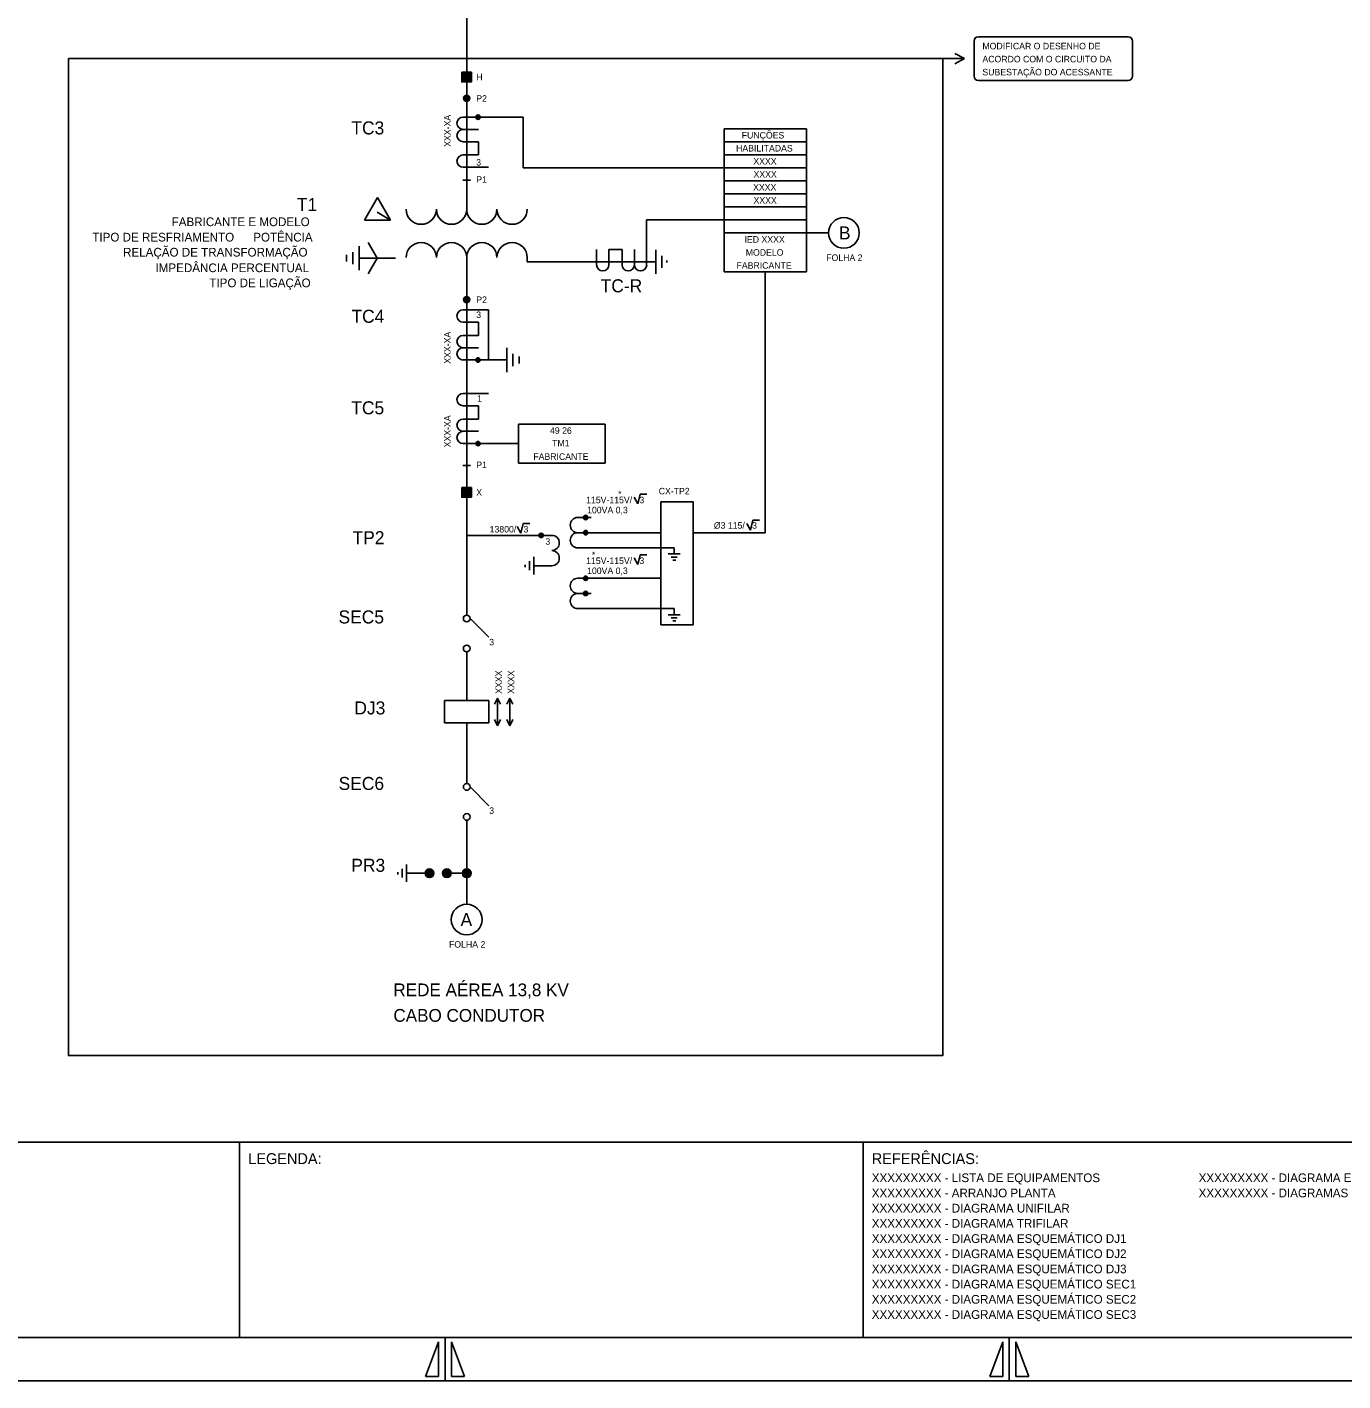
# Model space of a CAD drawing. Extents: x 400 to 1404, y 358 to 952.
# Drawn here: x 807.3 to 1110.5, y 358 to 669.8 of the extents above; entities that cross this region are included whole.
import ezdxf

# ---------------------------------------------------------------- set-up
doc = ezdxf.new("R2010")
doc.units = 0
doc.layers.add('New Level (0)', color=7, linetype='Continuous')

# ---------------------------------------------------------------- blocks, each defined once
blk = doc.blocks.new('_U3')
for p, q in [((-1.47, 0.42), (-0.62, -1.12)), ((-0.62, -1.12), (-0.07, 1.12)), ((-0.07, 1.12), (1.47, 1.12))]:
    blk.add_line(p, q)

msp = doc.modelspace()

# ---------------------------------------------------------------- linework, layer by layer
for p, q in [((908.57, 627.47), (908.57, 672.04)), ((907.45, 657.26), (909.61, 659.41)), ((907.45, 657.44), (909.43, 659.41)), ((907.45, 657.61), (909.25, 659.41)), ((907.45, 657.79), (909.08, 659.41)), ((907.45, 657.97), (908.9, 659.41)), ((907.45, 658.14), (908.72, 659.41)), ((907.45, 658.32), (908.54, 659.41)), ((907.45, 658.5), (908.37, 659.41)), ((907.45, 658.67), (908.19, 659.41)), ((907.45, 658.85), (908.01, 659.41)), ((907.45, 659.03), (907.84, 659.41)), ((907.45, 659.2), (907.66, 659.41)), ((907.45, 659.38), (907.48, 659.41)), ((907.57, 657.2), (909.66, 659.29)), ((907.75, 657.2), (909.66, 659.12)), ((907.92, 657.2), (909.66, 658.94)), ((908.1, 657.2), (909.66, 658.76)), ((908.28, 657.2), (909.66, 658.59)), ((908.46, 657.2), (909.66, 658.41)), ((908.63, 657.2), (909.66, 658.23)), ((908.81, 657.2), (909.66, 658.06)), ((908.99, 657.2), (909.66, 657.88)), ((909.16, 657.2), (909.66, 657.7)), ((909.34, 657.2), (909.66, 657.53)), ((909.52, 657.2), (909.66, 657.35)), ((907.75, 649.07), (921.57, 649.07)), ((921.57, 637.41), (921.57, 649.07)), ((907.75, 646.24), (911.29, 646.24)), ((967.89, 646.41), (967.89, 613.41)), ((986.87, 646.41), (967.89, 646.41)), ((986.87, 646.41), (986.87, 613.41)), ((907.75, 643.41), (911.29, 643.41)), ((911.29, 640.36), (911.29, 643.41)), ((986.87, 643.41), (967.89, 643.41)), ((907.75, 640.36), (911.29, 640.36)), ((986.87, 640.41), (967.89, 640.41)), ((907.75, 637.53), (913.62, 637.53)), ((921.57, 637.41), (968.49, 637.41)), ((986.87, 637.41), (967.89, 637.41)), ((986.87, 634.41), (967.89, 634.41)), ((884.99, 625.33), (888.02, 630.57)), ((888.02, 630.57), (891.04, 625.33)), ((986.87, 631.41), (967.89, 631.41)), ((891.04, 625.33), (887.95, 627.21)), ((986.87, 628.41), (967.89, 628.41)), ((986.87, 628.41), (967.89, 628.41)), ((891.04, 625.33), (884.99, 625.33)), ((950.04, 615.06), (950.04, 625.41)), ((950.04, 625.41), (967.89, 625.41)), ((986.87, 625.41), (967.89, 625.41)), ((991.94, 622.41), (967.89, 622.41)), ((882.37, 617.99), (882.37, 615.2)), ((883.76, 613.8), (883.76, 619.39)), ((887.95, 616.6), (885.86, 620.22)), ((938.5, 615.06), (938.5, 618.59)), ((941.33, 618.59), (944.38, 618.59)), ((941.33, 615.06), (941.33, 618.59)), ((944.38, 615.06), (944.38, 618.59)), ((947.21, 615.06), (947.21, 618.59)), ((952.16, 618.54), (952.16, 612.96)), ((880.89, 615.82), (880.89, 617.38)), ((892.14, 616.6), (883.76, 616.6)), ((887.95, 616.6), (885.86, 612.97)), ((922.53, 616.71), (922.53, 615.75)), ((922.53, 615.75), (952.16, 615.75)), ((953.55, 614.35), (953.55, 617.15)), ((954.72, 616.09), (954.72, 615.56)), ((986.87, 613.41), (967.89, 613.41)), ((977.38, 553.35), (977.38, 613.41)), ((907.75, 604.68), (913.62, 604.68)), ((907.75, 601.85), (911.29, 601.85)), ((907.75, 598.8), (911.29, 598.8)), ((911.29, 601.85), (911.29, 598.8)), ((907.75, 595.97), (911.29, 595.97)), ((917.81, 590.35), (917.81, 595.93)), ((907.75, 593.14), (911.29, 593.14)), ((911.29, 593.14), (917.81, 593.14)), ((919.2, 594.54), (919.2, 591.74)), ((920.68, 592.36), (920.68, 593.92)), ((907.75, 585.42), (913.62, 585.42)), ((907.75, 582.59), (911.29, 582.59)), ((911.29, 582.59), (911.29, 579.54)), ((907.75, 579.54), (911.29, 579.54)), ((920.5, 578.38), (920.5, 569.38)), ((920.5, 578.38), (940.48, 578.38)), ((940.48, 578.38), (940.48, 569.38)), ((907.75, 576.71), (911.29, 576.71)), ((907.75, 573.88), (920.5, 573.88)), ((907.75, 573.88), (911.29, 573.88)), ((920.5, 569.38), (940.48, 569.38)), ((907.45, 561.58), (909.61, 563.73)), ((907.45, 561.75), (909.43, 563.73)), ((907.45, 561.93), (909.25, 563.73)), ((907.45, 562.11), (909.08, 563.73)), ((907.45, 562.28), (908.9, 563.73)), ((907.45, 562.46), (908.72, 563.73)), ((907.45, 562.64), (908.54, 563.73)), ((907.45, 562.81), (908.37, 563.73)), ((907.45, 562.99), (908.19, 563.73)), ((907.45, 563.17), (908.01, 563.73)), ((907.45, 563.35), (907.84, 563.73)), ((907.45, 563.52), (907.66, 563.73)), ((907.45, 563.7), (907.48, 563.73)), ((907.57, 561.52), (909.66, 563.61)), ((907.75, 561.52), (909.66, 563.44)), ((907.92, 561.52), (909.66, 563.26)), ((908.1, 561.52), (909.66, 563.08)), ((908.28, 561.52), (909.66, 562.9)), ((908.46, 561.52), (909.66, 562.73)), ((908.63, 561.52), (909.66, 562.55)), ((908.81, 561.52), (909.66, 562.37)), ((908.99, 561.52), (909.66, 562.2)), ((909.16, 561.52), (909.66, 562.02)), ((909.34, 561.52), (909.66, 561.84)), ((909.52, 561.52), (909.66, 561.67)), ((934.17, 556.85), (937.28, 556.85)), ((908.58, 552.74), (928.17, 552.74)), ((934.17, 553.35), (953.31, 553.35)), ((960.79, 553.35), (977.38, 553.35)), ((934.17, 549.85), (956.4, 549.85)), ((956.4, 549.85), (956.4, 548.45)), ((922.04, 545.98), (922.04, 545.44)), ((923.05, 544.71), (923.05, 546.76)), ((924.08, 547.78), (924.08, 543.69)), ((957.8, 548.45), (955, 548.45)), ((955.7, 547.75), (957.1, 547.75)), ((956.06, 547.05), (956.74, 547.05)), ((928.17, 545.74), (924.08, 545.74)), ((953.31, 542.86), (934.17, 542.86)), ((934.17, 539.36), (937.28, 539.36)), ((913.67, 529.25), (909.34, 533.59)), ((934.17, 535.86), (956.4, 535.86)), ((957.8, 534.46), (955, 534.46)), ((955.7, 533.76), (957.1, 533.76)), ((956.4, 535.86), (956.4, 534.46)), ((956.06, 533.06), (956.74, 533.06)), ((903.45, 509.59), (903.45, 514.71)), ((903.45, 514.71), (913.69, 514.71)), ((913.69, 514.71), (913.69, 509.59)), ((915.69, 515.25), (914.98, 513.84)), ((915.69, 508.88), (915.69, 515.25)), ((915.69, 515.25), (916.39, 513.84)), ((918.54, 515.25), (917.83, 513.84)), ((918.54, 508.88), (918.54, 515.25)), ((918.54, 515.25), (919.24, 513.84)), ((913.69, 509.59), (903.45, 509.59)), ((915.69, 508.88), (914.98, 510.3)), ((915.69, 508.88), (916.39, 510.3)), ((918.54, 508.88), (917.83, 510.3)), ((918.54, 508.88), (919.24, 510.3)), ((913.68, 490.44), (909.34, 494.78)), ((892.68, 475.19), (892.68, 474.59)), ((892.68, 474.89), (892.68, 474.89)), ((893.68, 475.89), (893.68, 473.89)), ((894.68, 472.89), (894.68, 476.89)), ((896, 474.89), (894.68, 474.89)), ((900, 474.89), (896, 474.89)), ((908.58, 474.89), (904, 474.89))]:
    msp.add_line(p, q)
for points in [[(907.45, 659.41), (909.66, 659.41), (909.66, 657.2), (907.45, 657.2)], [(907.45, 563.73), (909.66, 563.73), (909.66, 561.52), (907.45, 561.52)]]:
    msp.add_lwpolyline(points, close=True)
for centre, radius in [((908.56, 653.41), 0.729), ((908.57, 653.4), 0.511), ((908.57, 653.4), 0.288), ((911.2, 649.07), 0.511), ((911.2, 649.07), 0.288), ((908.56, 607.04), 0.729), ((908.57, 607.04), 0.511), ((908.57, 607.04), 0.288), ((911.2, 593.14), 0.511), ((911.2, 593.14), 0.288), ((911.2, 573.88), 0.511), ((911.2, 573.88), 0.288), ((935.97, 556.85), 0.511), ((935.97, 556.85), 0.288), ((925.73, 552.73), 0.511), ((925.73, 552.73), 0.288), ((935.97, 553.35), 0.511), ((935.97, 553.35), 0.288), ((935.97, 542.86), 0.511), ((935.97, 542.86), 0.288), ((935.97, 539.36), 0.511), ((935.97, 539.36), 0.288), ((908.57, 533.59), 0.768), ((908.57, 526.68), 0.768), ((908.58, 494.78), 0.768), ((908.58, 487.87), 0.768), ((900, 474.89), 1), ((900, 474.89), 0.75), ((900, 474.89), 0.5), ((900, 474.89), 0.25), ((904, 474.89), 1), ((904, 474.89), 0.75), ((904, 474.89), 0.5), ((904, 474.89), 0.25), ((908.58, 474.89), 1), ((908.58, 474.89), 0.75), ((908.58, 474.89), 0.5), ((908.58, 474.89), 0.25)]:
    msp.add_circle(centre, radius)
for centre, radius, start, end in [((907.75, 647.66), 1.42, 90, 270), ((907.75, 644.83), 1.42, 90, 270), ((907.75, 638.94), 1.42, 90, 270), ((898.09, 627.88), 3.49, 180, 0), ((905.08, 627.88), 3.49, 180, 0), ((912.06, 627.88), 3.49, 180, 0), ((919.04, 627.88), 3.49, 180, 0), ((898.09, 616.71), 3.49, 0, 180), ((905.08, 616.71), 3.49, 0, 180), ((912.06, 616.71), 3.49, 0, 180), ((919.04, 616.71), 3.49, 0, 180), ((939.92, 615.06), 1.42, 180, 0), ((945.8, 615.06), 1.42, 180, 0), ((948.63, 615.06), 1.42, 180, 0), ((907.75, 603.27), 1.42, 90, 270), ((907.75, 597.38), 1.42, 90, 270), ((907.75, 594.55), 1.42, 90, 270), ((907.75, 584), 1.42, 90, 270), ((907.75, 578.12), 1.42, 90, 270), ((907.75, 575.29), 1.42, 90, 270), ((934.17, 555.1), 1.75, 90, 270), ((928.17, 550.99), 1.75, 270, 90), ((934.17, 551.6), 1.75, 90, 270), ((928.17, 547.49), 1.75, 270, 90), ((934.17, 541.11), 1.75, 90, 270), ((934.17, 537.61), 1.75, 90, 270)]:
    msp.add_arc(centre, radius, start, end)
at = {"layer": 'New Level (0)'}
for p, q in [((1026.47, 667.61), (1033.82, 667.61)), ((1033.82, 667.61), (1061.01, 667.61)), ((1025.47, 658.5), (1025.47, 666.61)), ((1062.01, 666.61), (1062.01, 658.5)), ((1018.28, 662.55), (1023.31, 662.55)), ((1023.31, 662.55), (1021.02, 663.76)), ((1023.31, 662.55), (1021.02, 661.34)), ((1061.01, 657.5), (1026.47, 657.5)), ((907.68, 634.57), (909.47, 634.57)), ((908.57, 616.71), (908.57, 534.36)), ((913.62, 593.14), (913.62, 604.68)), ((907.68, 568.85), (909.47, 568.85)), ((908.57, 525.91), (908.57, 514.71)), ((908.57, 509.59), (908.57, 495.55)), ((908.57, 487.11), (908.57, 467.77)), ((572.58, 412.96), (1393.58, 412.96)), ((856.24, 412.96), (856.24, 367.96)), ((999.91, 412.96), (999.91, 367.96)), ((572.58, 367.96), (1393.58, 367.96)), ((572.58, 367.96), (1393.58, 367.96)), ((899.08, 358.96), (902.08, 366.96)), ((902.08, 366.96), (902.08, 358.96)), ((903.58, 367.96), (903.58, 357.96)), ((905.08, 366.96), (905.08, 358.96)), ((908.08, 358.96), (905.08, 366.96)), ((1029.08, 358.96), (1032.08, 366.96)), ((1032.08, 366.96), (1032.08, 358.96)), ((1033.58, 367.96), (1033.58, 357.96)), ((1035.08, 366.96), (1035.08, 358.96)), ((1038.08, 358.96), (1035.08, 366.96)), ((902.08, 358.96), (899.08, 358.96)), ((905.08, 358.96), (908.08, 358.96)), ((1032.08, 358.96), (1029.08, 358.96)), ((1035.08, 358.96), (1038.08, 358.96)), ((562.58, 357.96), (1403.58, 357.96)), ((562.58, 357.96), (1403.58, 357.96))]:
    msp.add_line(p, q, dxfattribs=at)
for points in [[(816.8, 662.55), (1018.28, 662.55), (1018.28, 432.9), (816.8, 432.9)], [(953.31, 560.45), (960.79, 560.45), (960.79, 532.16), (953.31, 532.16)]]:
    msp.add_lwpolyline(points, close=True, dxfattribs=at)
for centre in [(995.49, 622.41), (908.57, 464.23)]:
    msp.add_circle(centre, 3.54, dxfattribs=at)
for centre, start, end in [((1026.47, 666.61), 90, 180), ((1061.01, 666.61), 0, 90), ((1026.47, 658.5), 180, 270), ((1061.01, 658.5), 270, 0)]:
    msp.add_arc(centre, 1, start, end, dxfattribs=at)

# ---------------------------------------------------------------- block references
for p in [(948.6, 561.1), (921.67, 554.37), (974.58, 555.08), (948.6, 547.11)]:
    msp.add_blockref('_U3', p)

# ---------------------------------------------------------------- texts
for s, height, p in [('MODIFICAR O DESENHO DE ', 1.5, (1027.41, 664.7)), ('ACORDO COM O CIRCUITO DA ', 1.5, (1027.41, 661.7)), ('H', 1.5, (910.78, 657.56)), ('SUBESTAÇÃO DO ACESSANTE', 1.5, (1027.41, 658.7)), ('P2', 1.5, (910.78, 652.63)), ('TC3', 3, (882, 645.1)), ('FUNÇÕES ', 1.5, (971.95, 644.16)), ('HABILITADAS', 1.5, (970.65, 641.16)), ('3', 1.5, (910.77, 637.93)), ('XXXX', 1.5, (974.63, 638.16)), ('XXXX', 1.5, (974.67, 635.16)), ('P1', 1.5, (910.78, 633.95)), ('XXXX', 1.5, (974.57, 632.16)), ('T1', 3, (869.44, 627.44)), ('XXXX', 1.5, (974.67, 629.16)), ('FABRICANTE E MODELO', 2, (840.59, 623.97)), ('B', 3, (994.35, 620.91)), ('TIPO DE RESFRIAMENTO ', 2, (822.31, 620.43)), ('POTÊNCIA', 2, (859.39, 620.43)), ('IED XXXX', 1.5, (972.6, 620.16)), ('RELAÇÃO DE TRANSFORMAÇÃO', 2, (829.4, 616.96)), ('MODELO', 1.5, (972.88, 617.16)), ('IMPEDÂNCIA PERCENTUAL', 2, (836.87, 613.37)), ('FABRICANTE', 1.5, (970.75, 614.16)), ('FOLHA 2', 1.5, (991.42, 615.95)), ('TIPO DE LIGAÇÃO', 2, (849.28, 609.9)), ('TC-R', 3, (939.44, 608.72)), ('P2', 1.5, (910.78, 606.27)), ('TC4', 3, (882.02, 601.7)), ('3', 1.5, (910.77, 602.8)), ('TC5', 3, (881.98, 580.62)), ('1', 1.5, (910.99, 583.53)), ('49 26', 1.5, (927.77, 576.13)), ('TM1', 1.5, (928.25, 573.24)), ('FABRICANTE', 1.5, (923.93, 570.13)), ('P1', 1.5, (910.78, 568.22)), ('X', 1.5, (910.78, 561.88)), ('115V-115V/   3', 1.5, (936.1, 560.13)), ('*', 1.5, (943.46, 561.55)), ('CX-TP2', 1.5, (952.82, 562.18)), ('100VA 0,3', 1.5, (936.32, 557.82)), ('Ø3 115/   3', 1.5, (965.52, 554.28)), ('TP2', 3, (882.27, 550.7)), ('13800/   3', 1.5, (913.86, 553.4)), ('3', 1.5, (926.71, 550.59)), ('*', 1.5, (937.43, 547.5)), ('115V-115V/   3', 1.5, (936.1, 546.14)), ('100VA 0,3', 1.5, (936.32, 543.83)), ('SEC5', 3, (879.04, 532.44)), ('3', 1.5, (913.76, 527.39)), ('DJ3', 3, (882.7, 511.48)), ('SEC6', 3, (879.06, 494.09)), ('3', 1.5, (913.77, 488.58)), ('PR3', 3, (881.99, 475.24)), ('A', 3, (907.16, 462.73)), ('FOLHA 2', 1.5, (904.5, 457.77)), ('REDE AÉREA 13,8 KV', 2.94, (891.69, 446.57)), ('CABO CONDUTOR ', 2.94, (891.69, 440.69))]:
    msp.add_text(s, height=height).set_placement(p)
for s, p in [('XXX-XA', (904.88, 642.25)), ('XXX-XA', (904.88, 592.28)), ('XXX-XA', (904.88, 573.02)), ('XXXX', (916.69, 516.25)), ('XXXX', (919.54, 516.25))]:
    msp.add_text(s, height=1.5, rotation=90).set_placement(p)
for s, height, p in [('LEGENDA:', 2.5, (858.24, 407.91)), ('REFERÊNCIAS:', 2.5, (1001.91, 407.91)), ('XXXXXXXXX - LISTA DE EQUIPAMENTOS', 2, (1001.91, 403.75)), ('XXXXXXXXX - DIAGRAMA ESQUEMÁTICO SEC4', 2, (1077.23, 403.75)), ('XXXXXXXXX - DIAGRAMAS LÓGICOS', 2, (1077.23, 400.25)), ('XXXXXXXXX - ARRANJO PLANTA', 2, (1001.91, 400.25)), ('XXXXXXXXX - DIAGRAMA UNIFILAR', 2, (1001.91, 396.75)), ('XXXXXXXXX - DIAGRAMA TRIFILAR', 2, (1001.91, 393.25)), ('XXXXXXXXX - DIAGRAMA ESQUEMÁTICO DJ1', 2, (1001.91, 389.75)), ('XXXXXXXXX - DIAGRAMA ESQUEMÁTICO DJ2', 2, (1001.91, 386.25)), ('XXXXXXXXX - DIAGRAMA ESQUEMÁTICO DJ3', 2, (1001.91, 382.75)), ('XXXXXXXXX - DIAGRAMA ESQUEMÁTICO SEC1', 2, (1001.91, 379.25)), ('XXXXXXXXX - DIAGRAMA ESQUEMÁTICO SEC2', 2, (1001.91, 375.75)), ('XXXXXXXXX - DIAGRAMA ESQUEMÁTICO SEC3', 2, (1001.91, 372.25))]:
    msp.add_text(s, height=height, dxfattribs=at).set_placement(p)

doc.saveas('drawing.dxf')
